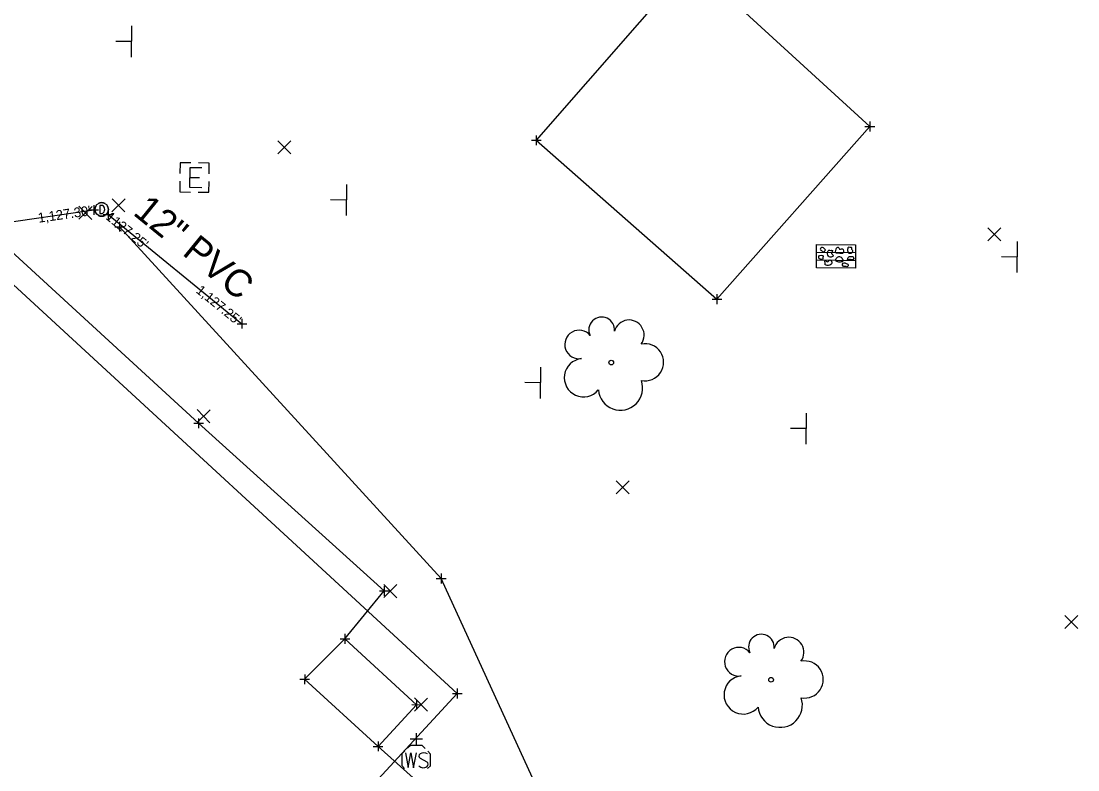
# Model space of a CAD drawing. Extents: x 142461 to 147261, y 511126 to 514697.
# Drawn here: x 145268.4 to 145377, y 512973.1 to 513050 of the extents above; entities that cross this region are included whole.
import ezdxf

# ---------------------------------------------------------------- set-up
doc = ezdxf.new("R2010")
doc.units = 0
for name, color, linetype in [('BD_X_Building', 7, 'Continuous'), ('DR_X_Cells', 7, 'Continuous'), ('DR_X_Elev_Flow', 7, 'Continuous'), ('DR_X_Storm_Sewer', 7, 'Continuous'), ('DR_X_Text', 7, 'Continuous'), ('GK_Drainage_Nodes', 7, 'Continuous'), ('PV_X_Walk', 7, 'Continuous'), ('RD_X_Cells', 7, 'Continuous'), ('SC_Scratch1', 7, 'Continuous'), ('SN_X_Public', 7, 'Continuous'), ('SV_X_Random_Point', 7, 'Continuous'), ('SV_X_Shot_Marker', 7, 'Continuous'), ('SV_X_Toe_of_Slope', 7, 'Continuous'), ('UT_X_Electric_Cells', 7, 'Continuous'), ('UT_X_Water_Cells', 7, 'Continuous'), ('VG_X_Cells', 7, 'Continuous')]:
    doc.layers.add(name, color=color, linetype=linetype)

msp = doc.modelspace()

# ---------------------------------------------------------------- linework, layer by layer
at = {"layer": 'BD_X_Building'}
for points in [[(145337.25, 513055.99), (145321.35, 513037.76), (145339.91, 513021.43), (145355.62, 513039.18)], [(145253.97, 512916.68), (145313.24, 512980.9), (145266.75, 513023.71), (145207.7, 512958.7)]]:
    msp.add_lwpolyline(points, close=True, dxfattribs=at)
at = {"layer": 'DR_X_Cells'}
msp.add_lwpolyline([(145276.8, 513031.05), (145276.52, 513031.05), (145276.52, 513030.25), (145276.8, 513030.25)], dxfattribs=at)
for centre, radius, start, end in [((145276.7, 513030.65), 0.7, 150.0184, 209.9816), ((145276.7, 513030.65), 0.7, 60.0184, 120.0157), ((145276.54, 513030.65), 0.474, 302.5148, 57.4852), ((145276.7, 513030.65), 0.7, 330.0184, 29.9816), ((145276.7, 513030.65), 0.7, 239.9843, 299.9816)]:
    msp.add_arc(centre, radius, start, end, dxfattribs=at)
at = {"layer": 'DR_X_Elev_Flow'}
for p, q in [((145275.88, 513031.1), (145275.88, 513030.1)), ((145275.38, 513030.6), (145276.38, 513030.6)), ((145275.88, 513030.6), (145275.88, 513030.6)), ((145276.86, 513030.12), (145277.86, 513030.12)), ((145277.36, 513030.62), (145277.36, 513029.62)), ((145277.36, 513030.12), (145277.36, 513030.12)), ((145290.61, 513018.91), (145291.61, 513018.91)), ((145291.11, 513019.41), (145291.11, 513018.41)), ((145291.11, 513018.91), (145291.11, 513018.91))]:
    msp.add_line(p, q, dxfattribs=at)
at = {"layer": 'DR_X_Storm_Sewer'}
for p, q in [((145195.78, 513019.06), (145275.88, 513030.6)), ((145277.36, 513030.12), (145291.11, 513018.91))]:
    msp.add_line(p, q, dxfattribs=at)
at = {"layer": 'GK_Drainage_Nodes'}
msp.add_line((145276.7, 513030.65), (145276.7, 513030.65), dxfattribs=at)
msp.add_line((145276.7, 513030.65), (145276.7, 513030.65), dxfattribs=at)
msp.add_line((145276.7, 513030.65), (145276.7, 513030.65), dxfattribs=at)
msp.add_line((145276.7, 513030.65), (145276.7, 513030.65), dxfattribs=at)
msp.add_line((145276.7, 513030.65), (145276.7, 513030.65), dxfattribs=at)
msp.add_circle((145276.7, 513030.65), 0.7, dxfattribs=at)
at = {"layer": 'PV_X_Walk'}
for p, q in [((145286.66, 513008.67), (145266.56, 513027.15)), ((145305.74, 512991.45), (145286.66, 513008.67)), ((145301.7, 512986.52), (145305.74, 512991.45)), ((145297.55, 512982.37), (145301.7, 512986.52)), ((145305.1, 512975.47), (145297.55, 512982.37)), ((145309.35, 512971.64), (145305.1, 512975.47))]:
    msp.add_line(p, q, dxfattribs=at)
msp.add_lwpolyline([(145305.1, 512975.47), (145309.05, 512979.75), (145301.7, 512986.52)], dxfattribs=at)
at = {"layer": 'RD_X_Cells'}
for p, q in [((145350.13, 513025.46), (145354.13, 513025.42)), ((145350.14, 513026.26), (145354.14, 513026.22)), ((145352.14, 513025.84), (145352.14, 513025.84))]:
    msp.add_line(p, q, dxfattribs=at)
msp.add_lwpolyline([(145350.15, 513027.06), (145354.15, 513027.02), (145354.13, 513024.62), (145350.13, 513024.66)], close=True, dxfattribs=at)
for points in [[(145350.6, 513026.46), (145350.53, 513026.57), (145350.58, 513026.68), (145350.77, 513026.73), (145350.95, 513026.62), (145351.07, 513026.46), (145350.96, 513026.38), (145350.77, 513026.29), (145350.63, 513026.46), (145350.6, 513026.46)], [(145351.41, 513026.46), (145351.3, 513026.34), (145351.37, 513025.85), (145351.73, 513025.77), (145351.85, 513025.91), (145351.67, 513026.21), (145351.74, 513026.31), (145351.78, 513026.44), (145351.54, 513026.45), (145351.41, 513026.46)], [(145352.19, 513026.66), (145352.12, 513026.45), (145352.12, 513026.19), (145352.49, 513026.15), (145352.81, 513026.14), (145352.87, 513026.52), (145352.71, 513026.62), (145352.52, 513026.56), (145352.42, 513026.72), (145352.33, 513026.78), (145352.19, 513026.66)], [(145353.57, 513026.79), (145353.44, 513026.78), (145353.4, 513026.73), (145353.37, 513026.58), (145353.36, 513026.47), (145353.38, 513026.3), (145353.42, 513026.2), (145353.49, 513026.14), (145353.6, 513026.11), (145353.68, 513026.13), (145353.77, 513026.19), (145353.84, 513026.32), (145353.85, 513026.44), (145353.75, 513026.56), (145353.72, 513026.65), (145353.72, 513026.73), (145353.64, 513026.78), (145353.57, 513026.79)], [(145350.79, 513025.7), (145350.84, 513025.89), (145350.62, 513025.94), (145350.39, 513025.88), (145350.38, 513025.79), (145350.39, 513025.63), (145350.56, 513025.54), (145350.74, 513025.51), (145350.8, 513025.66), (145350.79, 513025.7)], [(145351, 513025.03), (145351.12, 513024.92), (145351.61, 513024.99), (145351.69, 513025.34), (145351.56, 513025.46), (145351.26, 513025.28), (145351.15, 513025.35), (145351.03, 513025.4), (145351.02, 513025.15), (145351, 513025.03)], [(145352.3, 513025.74), (145352.16, 513025.61), (145352.12, 513025.39), (145352.45, 513025.25), (145352.83, 513025.33), (145352.73, 513025.68), (145352.42, 513025.8), (145352.3, 513025.74)], [(145353.61, 513025.83), (145353.46, 513025.78), (145353.35, 513025.62), (145353.3, 513025.51), (145353.64, 513025.5), (145353.83, 513025.47), (145353.96, 513025.61), (145353.91, 513025.77), (145353.74, 513025.83), (145353.62, 513025.83), (145353.61, 513025.83)], [(145353.11, 513025.13), (145352.98, 513025.16), (145352.82, 513025.03), (145352.87, 513024.82), (145353.05, 513024.8), (145353.33, 513024.79), (145353.38, 513024.97), (145353.29, 513025.06), (145353.11, 513025.13)]]:
    msp.add_spline(points, degree=3, dxfattribs=at)
at = {"layer": 'SN_X_Public'}
for p, q in [((145279.76, 513049.51), (145279.73, 513046.31)), ((145279.75, 513047.91), (145278.15, 513047.92)), ((145279.75, 513047.91), (145279.75, 513047.91)), ((145301.84, 513033.22), (145301.81, 513030.02)), ((145301.82, 513031.62), (145300.22, 513031.64)), ((145301.82, 513031.62), (145301.82, 513031.62)), ((145370.74, 513027.36), (145370.71, 513024.16)), ((145370.73, 513025.76), (145369.13, 513025.77)), ((145370.73, 513025.76), (145370.73, 513025.76)), ((145321.79, 513014.43), (145321.76, 513011.23)), ((145321.78, 513012.83), (145320.18, 513012.85)), ((145321.77, 513012.83), (145321.77, 513012.83)), ((145349.08, 513009.73), (145349.04, 513006.53)), ((145349.06, 513008.13), (145347.46, 513008.14)), ((145349.06, 513008.13), (145349.06, 513008.13))]:
    msp.add_line(p, q, dxfattribs=at)
at = {"layer": 'SV_X_Random_Point'}
for p, q in [((145294.79, 513036.36), (145296.13, 513037.69)), ((145294.79, 513037.69), (145296.13, 513036.36)), ((145277.76, 513030.42), (145279.11, 513031.74)), ((145277.77, 513031.75), (145279.09, 513030.4)), ((145274.36, 513029.65), (145275.71, 513030.97)), ((145274.37, 513030.98), (145275.69, 513029.63)), ((145367.74, 513027.42), (145369.07, 513028.76)), ((145367.74, 513028.76), (145369.07, 513027.42)), ((145286.5, 513008.75), (145287.85, 513010.07)), ((145286.51, 513010.08), (145287.83, 513008.73)), ((145329.56, 513001.44), (145330.89, 513002.77)), ((145329.56, 513002.77), (145330.89, 513001.44)), ((145305.69, 512990.77), (145307.03, 512992.09)), ((145305.7, 512992.1), (145307.02, 512990.75)), ((145375.66, 512987.59), (145376.99, 512988.93)), ((145375.66, 512988.93), (145376.99, 512987.59)), ((145308.83, 512979.1), (145310.17, 512980.43)), ((145308.84, 512980.44), (145310.16, 512979.09))]:
    msp.add_line(p, q, dxfattribs=at)
at = {"layer": 'SV_X_Shot_Marker'}
for p, q in [((145355.62, 513039.68), (145355.62, 513038.68)), ((145321.35, 513038.26), (145321.35, 513037.26)), ((145355.12, 513039.18), (145356.12, 513039.18)), ((145355.62, 513039.18), (145355.62, 513039.18)), ((145320.85, 513037.76), (145321.85, 513037.76)), ((145321.35, 513037.76), (145321.35, 513037.76)), ((145278.04, 513028.87), (145279.04, 513028.87)), ((145278.54, 513029.37), (145278.54, 513028.37)), ((145278.54, 513028.87), (145278.54, 513028.87)), ((145339.41, 513021.43), (145340.41, 513021.43)), ((145339.91, 513021.93), (145339.91, 513020.93)), ((145339.91, 513021.43), (145339.91, 513021.43)), ((145286.66, 513009.17), (145286.65, 513008.17)), ((145286.16, 513008.68), (145287.16, 513008.67)), ((145286.66, 513008.67), (145286.66, 513008.67)), ((145311.08, 512992.72), (145312.08, 512992.72)), ((145311.58, 512993.22), (145311.58, 512992.22)), ((145311.58, 512992.72), (145311.58, 512992.72)), ((145305.74, 512991.95), (145305.73, 512990.95)), ((145305.24, 512991.46), (145306.24, 512991.45)), ((145305.74, 512991.45), (145305.74, 512991.45)), ((145301.2, 512986.52), (145302.2, 512986.51)), ((145301.7, 512987.02), (145301.69, 512986.02)), ((145301.7, 512986.52), (145301.7, 512986.52)), ((145297.05, 512982.37), (145298.05, 512982.36)), ((145297.56, 512982.87), (145297.55, 512981.87)), ((145297.55, 512982.37), (145297.55, 512982.37)), ((145312.74, 512980.9), (145313.74, 512980.9)), ((145313.24, 512981.4), (145313.24, 512980.4)), ((145313.24, 512980.9), (145313.24, 512980.9)), ((145308.55, 512979.76), (145309.55, 512979.75)), ((145309.06, 512980.25), (145309.05, 512979.25)), ((145309.05, 512979.75), (145309.05, 512979.75)), ((145304.6, 512975.47), (145305.6, 512975.46)), ((145305.11, 512975.97), (145305.1, 512974.97)), ((145305.1, 512975.47), (145305.1, 512975.47))]:
    msp.add_line(p, q, dxfattribs=at)
at = {"layer": 'SV_X_Toe_of_Slope'}
msp.add_lwpolyline([(145357.04, 512839.68), (145351.71, 512871.52), (145342.5, 512913.44), (145326.02, 512961.16), (145311.58, 512992.72), (145278.54, 513028.87)], dxfattribs=at)
at = {"layer": 'UT_X_Electric_Cells'}
for p, q in [((145285.74, 513033.94), (145286.74, 513033.93)), ((145286.24, 513033.93), (145286.24, 513033.93))]:
    msp.add_line(p, q, dxfattribs=at)
for points in [[(145285.85, 513035.43), (145284.75, 513035.45), (145284.74, 513034.35)], [(145287.74, 513034.32), (145287.75, 513035.42), (145286.65, 513035.43)], [(145287, 513034.92), (145285.75, 513034.94), (145285.73, 513032.94), (145286.98, 513032.92)], [(145284.73, 513033.55), (145284.72, 513032.45), (145285.82, 513032.44)], [(145286.62, 513032.43), (145287.72, 513032.42), (145287.73, 513033.52)]]:
    msp.add_lwpolyline(points, dxfattribs=at)
at = {"layer": 'UT_X_Water_Cells'}
for p, q in [((145309.03, 512975.57), (145309.04, 512976.84)), ((145309.67, 512976.2), (145308.4, 512976.21)), ((145309.42, 512974.25), (145310.12, 512973.87)), ((145309.02, 512974.09), (145309.02, 512974.09))]:
    msp.add_line(p, q, dxfattribs=at)
for points in [[(145309.93, 512975.25), (145309.62, 512975.56), (145308.44, 512975.57), (145308.13, 512975.28)], [(145307.85, 512975), (145307.54, 512974.7), (145307.53, 512973.51), (145307.83, 512973.21)], [(145307.92, 512974.81), (145308.18, 512973.28), (145308.48, 512974.8), (145308.75, 512973.27), (145309.05, 512974.8)], [(145310.18, 512973.18), (145310.49, 512973.48), (145310.5, 512974.66), (145310.2, 512974.97)]]:
    msp.add_lwpolyline(points, dxfattribs=at)
for centre, radius, start, end in [((145309.57, 512974.47), 0.271, 125.6674, 235.7762), ((145309.79, 512973.99), 0.8, 60.7549, 118.0623), ((145309.76, 512973.9), 0.633, 223.0781, 303.8049), ((145309.89, 512973.63), 0.339, 310.8969, 47.3445)]:
    msp.add_arc(centre, radius, start, end, dxfattribs=at)
at = {"layer": 'VG_X_Cells'}
for centre in [(145329.06, 513014.91), (145345.47, 512982.31)]:
    msp.add_circle(centre, 0.24, dxfattribs=at)
for centre, radius, start, end in [((145328.07, 513018.27), 1.32, 354.0047, 205.9741), ((145330.88, 513017.74), 1.55, 323.83, 165.0376), ((145325.75, 513016.77), 1.47, 39.0625, 279.5412), ((145332.52, 513014.94), 1.91, 259.1453, 101.4596), ((145326.2, 513013.36), 1.97, 96.1722, 320.5737), ((145330, 513012.3), 2.28, 184.9476, 19.4572), ((145344.48, 512985.67), 1.32, 354.0047, 205.9741), ((145347.29, 512985.13), 1.55, 323.83, 165.0376), ((145342.16, 512984.17), 1.47, 39.0625, 279.5412), ((145348.93, 512982.34), 1.91, 259.1453, 101.4596), ((145342.61, 512980.76), 1.97, 96.1722, 320.5737), ((145346.41, 512979.7), 2.28, 184.9476, 19.4572)]:
    msp.add_arc(centre, radius, start, end, dxfattribs=at)

# ---------------------------------------------------------------- texts
at = {"layer": 'DR_X_Text'}
msp.add_text('12" PVC', height=2.8, rotation=320.827, dxfattribs=at).set_placement((145279.81, 513030.19))
at = {"layer": 'SC_Scratch1'}
for s, rotation, p in [("1,127.30'", 8.1965, (145270.23, 513029.28)), ("1127.25'", 320.827, (145277.04, 513029.73)), ("1,127.25'", 320.827, (145286.31, 513022.18))]:
    msp.add_text(s, height=1, rotation=rotation, dxfattribs=at).set_placement(p)

doc.saveas('drawing.dxf')
